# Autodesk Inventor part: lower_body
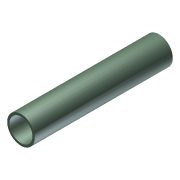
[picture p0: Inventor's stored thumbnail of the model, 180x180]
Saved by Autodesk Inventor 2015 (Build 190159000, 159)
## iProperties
Created: 2020-09
Part Number: lower_body
Material: 一般
Document SubType Name: Modeling
Designer: 徐冠倫
Mass: 2073.45 g
Surface Area: 4216.02 cm^2
Volume: 2073.45 cm^3
Density: 1 g/cm^3
Appearance: 預設
Author: 徐冠倫
Author: IANNIAN
Title: D:\Desktop\OCW-Computer-Aided Engineering Drawing\OCW_Topic 06：組合圖與機構模擬(進階)\6-1_Flexibility\Mechanical Gripper(piston)\Mechanical Gripper(STP)\cylinder2.stp
Creation Date: 2020-09-04
Sending System: Autodesk Inventor 2020
Preprocessor: ST-DEVELOPER v18
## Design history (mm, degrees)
node "lower_body1"
body "Solid1"
node "Base1"
